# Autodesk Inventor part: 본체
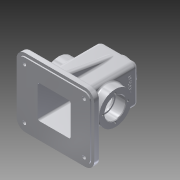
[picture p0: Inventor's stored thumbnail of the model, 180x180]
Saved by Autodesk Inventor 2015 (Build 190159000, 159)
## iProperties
Created: 2016-02
Part Number: 본체
Material: 알루미늄 6061
Document SubType Name: Modeling
Designer: Administrator
Density: 2.7 g/cm^3
Appearance: 알루미늄 - 평지
Mass: 855.756 g
Surface Area: 916.106 cm^2
Volume: 316.947 cm^3
Author: Administrator
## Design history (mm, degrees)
sketch "스케치1"
  geometry: L1 (65, 57.5)-(-65, 57.5); L2 (-65, 57.5)-(-65, -57.5); L3 (-65, -57.5)-(65, -57.5); L4 (65, -57.5)-(65, 57.5); L5 (65, 57.5)-(-65, -57.5); L6 (-65, 57.5)-(65, -57.5); 1 further point
  constraints: 12 end point, 2 midpoint, 2 parallel, 1 horizontal, 1 perpendicular
  dimensions: "d0" = 130 distance of L2.end L3.end; "d1" = 115 distance of L1.end L2.end
extrude "돌출1" new body sketch "스케치1" distance "d2" = 10; taper "d3" = 0 deg
sketch "스케치2"
  geometry: L1 (-60, -52.5)-(60, -52.5); L2 (60, -52.5)-(60, 52.5); L3 (60, 52.5)-(-60, 52.5); L4 (-60, 52.5)-(-60, -52.5); L5 (-60, -52.5)-(60, 52.5); L6 (60, -52.5)-(-60, 52.5); 1 further point
  constraints: 12 end point, 2 midpoint, 2 parallel, 1 horizontal, 1 perpendicular
  dimensions: "d4" = 120 distance of L2.end L3.end; "d5" = 105 distance of L1.end L2.end
extrude "돌출2" join sketch "스케치2" distance "d6" = 2; taper "d7" = 0 deg
node "작업 평면2"
sketch "스케치5"
  geometry: L1 (32.5, 32.5)-(-32.5, 32.5); L2 (-32.5, 32.5)-(-32.5, -32.5); L3 (-32.5, -32.5)-(32.5, -32.5); L4 (32.5, -32.5)-(32.5, 32.5); L5 (32.5, 32.5)-(-32.5, -32.5); L6 (-32.5, 32.5)-(32.5, -32.5); L7 (-65, -57.5)-(65, -57.5) reference; L8 (65, -57.5)-(65, 57.5) reference; L9 (65, 57.5)-(-65, 57.5) reference; L10 (-65, 57.5)-(-65, -57.5) reference; 1 further point
  constraints: 12 end point, 2 midpoint, 2 parallel, 1 horizontal, 1 perpendicular
  dimensions: "d12" = 25 distance between parallel lines of L7 L3; "d13" = 65 distance between parallel lines of L2 L4
extrude "돌출3" join sketch "스케치5" stored distance "d14" = 108; taper "d15" = 0 deg
node "작업 평면3"
sketch "스케치6"
  geometry: L1 (-2, -52.5)-(-2, 52.5) reference; C1 r 27.5 at (53, 0); 1 further point
  constraints: 1 centre point, 1 horizontal alignment
  dimensions: "d17" = 55 diameter of C1; "d18" = 55 distance from line of C1.centre L1
extrude "돌출4" join sketch "스케치6" stored distance "d19" = 95; taper "d20" = 0 deg
sketch "스케치7"
  geometry: L1 (-47.5, 25.5)-(-32.5, 25.5) reference; L2 (65, 10)-(-65, 10) reference; L3 (-42.5, 25.5)-(-42.5, 10); L4 (-32.5, 10)-(-32.5, 108) reference; 1 further point
  constraints: 2 end point, 2 point on line, 1 perpendicular
  dimensions: "d21" = 10 distance between parallel lines of L4 L3
feature "리브1" sketch "스케치7" dims "d22" = 1, "d23" = 6, "d24" = 0, "d25" = 0, "d26" = 1, "d27" = 1
node "작업 평면4"
sketch "스케치8"
  geometry: C1 r 20 at (0, 0); 1 further point
  constraints: 1 centre point, 1 coincident
  dimensions: "d29" = 40 diameter of C1
extrude "돌출5" join sketch "스케치8" distance "d30" = 10; taper "d31" = -5 deg
node "작업 평면5"
sketch "스케치9"
  geometry: L1 (125, 0)-(5, 0) reference; L2 (130, 10)-(0, 10) reference; L3 (60, 102)-(70, 102); L4 (70, 102)-(70, 10); L5 (70, 10)-(60, 10); L6 (60, 10)-(60, 102); L7 (60, 102)-(70, 10); L8 (70, 102)-(60, 10); 6 further points
  constraints: 12 end point, 6 midpoint, 2 parallel, 1 coincident, 1 horizontal, 1 perpendicular, 1 vertical alignment
  dimensions: "d33" = 10 distance of L3.start L3.end; "d34" = 92 distance between parallel lines of L2 L3
extrude "돌출6" join sketch "스케치9" stored distance "d35" = 10; taper "d36" = 0 deg
node "작업 평면6"
feature "면 기울기1" dims angle "d38" = 10 deg
node "작업 평면7"
node "작업 평면8"
sketch "스케치10"
  geometry: L1 (108, -32.5)-(108, 32.5) reference; L2 (108, 32.5)-(10, 32.5) reference; L3 (10, -32.5)-(108, -32.5) reference; L4 (-2, 27.5)-(103, 27.5); L5 (103, 27.5)-(103, -27.5); L6 (103, -27.5)-(-2, -27.5); L7 (-2, 52.5)-(-2, -52.5) reference; L8 (-2, 27.5)-(-2, -27.5); 1 further point
  constraints: 8 end point, 2 point on line, 2 other
  dimensions: "d41" = 5 distance between parallel lines of L1 L5
extrude "돌출7" cut sketch "스케치10" stored distance "d42" = 55; taper "d43" = 0 deg
node "작업 평면9"
sketch "스케치11"
  geometry: L1 (47.5, 25.5)-(47.5, 80.5) reference; L2 (-47.5, 80.5)-(-47.5, 25.5) reference; L3 (-60, -2)-(60, -2) reference; L4 (-47.5, 53)-(47.5, 53); L5 (-47.5, 53)-(-47.5, 70.5); L6 (-47.5, 70.5)-(-30.5, 70.5); L7 (-30.5, 70.5)-(-30.5, 68); L8 (-30.5, 68)-(30.5, 68); L9 (30.5, 68)-(30.5, 70.5); L10 (30.5, 70.5)-(47.5, 70.5); L11 (47.5, 53)-(47.5, 70.5); 1 further point
  constraints: 16 end point, 4 perpendicular, 2 horizontal, 2 midpoint, 2 point on line, 1 collinear
  dimensions: "d45" = 55 distance between parallel lines of L3 L4; "d46" = 35 diameter of L6 L4; "d47" = 35 diameter of L10 L4; "d48" = 30 diameter of L8 L4; "d49" = 17 distance between parallel lines of L7 L2; "d50" = 17 distance between parallel lines of L1 L9
revolve "회전1" sketch "스케치11" stored, may be unused: angle "d51" = 90 deg
sketch "스케치12"
  geometry: C1 r 17.5 at (0, 0) reference; 2 further points
  constraints: 1 vertical alignment
  dimensions: "d52" = 21 distance of C1.centre point (0, 21)
hole "구멍1" sketch "스케치12" at (0, 21) diameter "d53" = 3.242; stored, may be unused: countersink angle "d57" = 90 deg, drill point angle "d59" = 118 deg; dims "d54" = 8, "d55" = 4, "d56" = 2, "d58" = 10
node "작업 평면10"
node "작업 평면11"
sketch "스케치13"
  geometry: L1 (118, 19.125)-(118, -19.125) reference; C1 r 17.5 at (53, 0) reference; 2 further points
  constraints: 1 horizontal alignment, 1 other
  dimensions: "d65" = 26 distance from line of point (92, 0) L1
feature "엠보싱1" sketch "스케치13" dims "d66" = 0.5, "d67" = 0
sketch "스케치14"
  geometry: C1 r 10.5 at (0, 0); 1 further point
  constraints: 1 centre point, 1 coincident
  dimensions: "d68" = 21 diameter of C1
extrude "돌출8" cut sketch "스케치14" distance "d69" = 55; taper "d70" = 0 deg
sketch "스케치15"
  geometry: 2 further points
  constraints: 1 horizontal alignment
  dimensions: "d71" = 14.5 distance of point (14.5, 0) point (0, 0)
hole "구멍2" sketch "스케치15" at (14.5, 0) diameter "d72" = 2.459; stored, may be unused: countersink angle "d76" = 90 deg, drill point angle "d78" = 118 deg; dims "d73" = 7, "d74" = 4, "d75" = 2, "d77" = 9
sketch "스케치16"
  geometry: L1 (-65, 57.5)-(-65, -57.5) reference; L2 (65, 57.5)-(-65, 57.5) reference; L3 (65, -57.5)-(65, 57.5) reference; L4 (-65, -57.5)-(65, -57.5) reference; C1 r 7.5 at (-50, 42.5); C2 r 7.5 at (50, 42.5); C3 r 7.5 at (50, -42.5); C4 r 7.5 at (-50, -42.5); 1 further point
  constraints: 4 centre point, 3 equal radius
  dimensions: "d82" = 15 distance from line of L1 C1.centre; "d83" = 15 distance from line of L2 C1.centre; "d84" = 15 diameter of C1; "d85" = 15 distance from line of L2 C2.centre; "d86" = 15 distance from line of L3 C2.centre; "d87" = 15 distance from line of C3.centre L3; "d88" = 15 distance from line of C3.centre L4; "d89" = 15 distance from line of L1 C4.centre; "d90" = 15 distance from line of L4 C4.centre
extrude "돌출9" join sketch "스케치16" distance "d91" = 1; taper "d92" = 0 deg
hole "구멍3" diameter "d95" = 6; stored, may be unused: countersink angle "d99" = 90 deg, drill point angle "d101" = 118 deg; dims "d93" = 10, "d94" = 10, "d96" = 6, "d97" = 4, "d98" = 2, "d100" = 9
hole "구멍4" diameter "d104" = 6; stored, may be unused: countersink angle "d108" = 90 deg, drill point angle "d110" = 118 deg; dims "d102" = 10, "d103" = 10, "d105" = 6, "d106" = 4, "d107" = 2, "d109" = 9
hole "구멍5" diameter "d113" = 6; stored, may be unused: countersink angle "d117" = 90 deg, drill point angle "d119" = 118 deg; dims "d111" = 10, "d112" = 10, "d114" = 6, "d115" = 4, "d116" = 2, "d118" = 9
hole "구멍6" diameter "d122" = 6; stored, may be unused: countersink angle "d126" = 90 deg, drill point angle "d128" = 118 deg; dims "d120" = 10, "d121" = 10, "d123" = 6, "d124" = 4, "d125" = 2, "d127" = 9
fillet "모깎기1" dims "d129" = 15
fillet "모깎기2" dims "d130" = 3
fillet "모깎기3" dims "d131" = 3
fillet "모깎기4" dims "d132" = 10
fillet "모깎기5" dims "d133" = 8
fillet "모깎기6" dims "d134" = 8
chamfer "모따기1" distance "d135" = 1; stored, may be unused: second distance "d136" = 2, angle "d137" = 45 deg
fillet "모깎기8" dims "d139" = 0.3
fillet "모깎기9" dims "d140" = 3
fillet "모깎기10" dims "d141" = 3
fillet "모깎기11" dims "d142" = 3
fillet "모깎기12" dims "d143" = 3
fillet "모깎기13" dims "d144" = 3
fillet "모깎기14" dims "d145" = 1
fillet "모깎기15" dims "d146" = 3
fillet "모깎기16" dims "d147" = 3
chamfer "모따기2" distance "d148" = 1; stored, may be unused: second distance "d149" = 2, angle "d150" = 45 deg
node "솔리드1"
mirror "대칭1"
mirror "대칭2"
pattern_circular "원형 패턴1" dims angle "d61" = 360 deg
mirror "대칭3"
pattern_circular "원형 패턴2" dims angle "d80" = 360 deg
other parameters: "d11" = 54, "d16" = 0, "d28" = 0, "d37" = 0, "d39" = 0, "d40" = 0, "d44" = 0, "d63" = 0
